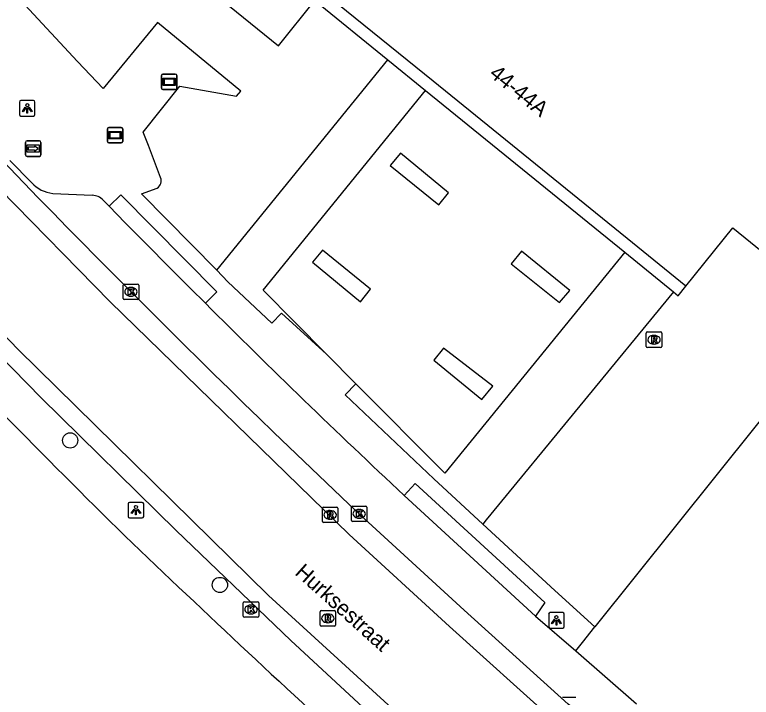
# Model space of a CAD drawing. Extents: x 157692 to 159670, y 381454 to 383289.
# Drawn here: x 157901.41 to 157948.81, y 382930.61 to 382974.54 of the extents above; entities that cross this region are included whole.
import ezdxf

# ---------------------------------------------------------------- set-up
doc = ezdxf.new("R2010")
doc.units = 0
for name, color, linetype in [('IMGEO_Boom', 7, 'Continuous'), ('IMGEO_Kolk', 7, 'Continuous'), ('IMGEO_Lichtpunt', 7, 'Continuous'), ('IMGEO_Openbare_ruimte_label', 7, 'Continuous'), ('IMGEO_Pand', 7, 'Continuous'), ('IMGEO_Pand_nummerreeks', 7, 'Continuous'), ('IMGEO_Parkeervlak_open', 7, 'Continuous'), ('IMGEO_Reclamebord', 7, 'Continuous'), ('IMGEO_Rijbaan_lokaal_gesloten', 7, 'Continuous'), ('IMGEO_Rijbaan_lokaal_open', 7, 'Continuous'), ('IMGEO_Rioolput', 7, 'Continuous'), ('IMGEO_Voetpad_open', 7, 'Continuous'), ('IMGEO_Wegwijzer', 7, 'Continuous')]:
    doc.layers.add(name, color=color, linetype=linetype)

msp = doc.modelspace()

# ---------------------------------------------------------------- linework, layer by layer
at = {"layer": 'IMGEO_Boom'}
for centre in [(157904.979, 382947.14), (157914.616, 382937.838)]:
    msp.add_circle(centre, 0.489, dxfattribs=at)
at = {"layer": 'IMGEO_Kolk'}
for p, q in [((157908.39, 382956.277), (157908.39, 382957.129)), ((157908.465, 382957.203), (157909.317, 382957.203)), ((157908.878, 382956.983), (157908.903, 382956.983)), ((157909.391, 382957.129), (157909.391, 382956.277)), ((157909.317, 382956.203), (157908.465, 382956.203)), ((157908.901, 382956.423), (157908.876, 382956.423)), ((157923.079, 382941.989), (157923.079, 382942.841)), ((157923.154, 382942.915), (157924.006, 382942.915)), ((157923.567, 382942.695), (157923.592, 382942.695)), ((157924.08, 382942.841), (157924.08, 382941.989)), ((157924.006, 382941.915), (157923.154, 382941.915)), ((157923.59, 382942.135), (157923.565, 382942.135)), ((157916.118, 382935.832), (157916.118, 382936.684)), ((157916.193, 382936.758), (157917.045, 382936.758)), ((157916.606, 382936.538), (157916.631, 382936.538)), ((157917.119, 382936.684), (157917.119, 382935.832)), ((157917.045, 382935.758), (157916.193, 382935.758)), ((157916.629, 382935.978), (157916.604, 382935.978)), ((157936.661, 382930.608), (157937.513, 382930.608))]:
    msp.add_line(p, q, dxfattribs=at)
for points in [[(157908.39, 382956.277), (157908.39, 382957.129)], [(157908.465, 382957.203), (157909.317, 382957.203)], [(157908.711, 382956.903), (157908.834, 382956.903), (157908.834, 382956.752), (157908.964, 382956.903), (157909.128, 382956.903), (157908.982, 382956.752), (157909.135, 382956.503), (157908.983, 382956.503), (157908.898, 382956.667), (157908.834, 382956.6), (157908.834, 382956.503), (157908.711, 382956.503), (157908.711, 382956.903)], [(157909.391, 382957.129), (157909.391, 382956.277)], [(157909.317, 382956.203), (157908.465, 382956.203)], [(157923.079, 382941.989), (157923.079, 382942.841)], [(157923.154, 382942.915), (157924.006, 382942.915)], [(157924.08, 382942.841), (157924.08, 382941.989)], [(157923.4, 382942.615), (157923.523, 382942.615), (157923.523, 382942.464), (157923.653, 382942.615), (157923.817, 382942.615), (157923.671, 382942.464), (157923.824, 382942.215), (157923.672, 382942.215), (157923.587, 382942.379), (157923.523, 382942.312), (157923.523, 382942.215), (157923.4, 382942.215), (157923.4, 382942.615)], [(157924.006, 382941.915), (157923.154, 382941.915)], [(157916.118, 382935.832), (157916.118, 382936.684)], [(157916.193, 382936.758), (157917.045, 382936.758)], [(157917.119, 382936.684), (157917.119, 382935.832)], [(157916.439, 382936.458), (157916.562, 382936.458), (157916.562, 382936.307), (157916.692, 382936.458), (157916.856, 382936.458), (157916.71, 382936.307), (157916.863, 382936.058), (157916.711, 382936.058), (157916.626, 382936.222), (157916.562, 382936.155), (157916.562, 382936.058), (157916.439, 382936.058), (157916.439, 382936.458)], [(157917.045, 382935.758), (157916.193, 382935.758)], [(157936.661, 382930.608), (157937.513, 382930.608)]]:
    msp.add_lwpolyline(points, dxfattribs=at)
for centre, start, end in [((157908.467, 382957.127), 91.552, 178.448), ((157908.467, 382957.127), 91.552, 178.448), ((157909.315, 382957.127), 1.552, 88.448), ((157909.315, 382957.127), 1.552, 88.448), ((157908.467, 382956.279), 181.552, 268.448), ((157908.467, 382956.279), 181.552, 268.448), ((157909.315, 382956.279), 271.552, 358.448), ((157909.315, 382956.279), 271.552, 358.448), ((157923.156, 382942.839), 91.552, 178.448), ((157923.156, 382942.839), 91.552, 178.448), ((157924.004, 382942.839), 1.552, 88.448), ((157924.004, 382942.839), 1.552, 88.448), ((157923.156, 382941.991), 181.552, 268.448), ((157923.156, 382941.991), 181.552, 268.448), ((157924.004, 382941.991), 271.552, 358.448), ((157924.004, 382941.991), 271.552, 358.448), ((157916.195, 382936.682), 91.552, 178.448), ((157916.195, 382936.682), 91.552, 178.448), ((157917.043, 382936.682), 1.552, 88.448), ((157917.043, 382936.682), 1.552, 88.448), ((157916.195, 382935.834), 181.552, 268.448), ((157916.195, 382935.834), 181.552, 268.448), ((157917.043, 382935.834), 271.552, 358.448), ((157917.043, 382935.834), 271.552, 358.448)]:
    msp.add_arc(centre, 0.0765, start, end, dxfattribs=at)
for centre, major_axis, ratio, start_param, end_param in [((157908.877, 382956.703), (-0.387, 0.002), 0.722429, 4.712389, 7.853982), ((157908.902, 382956.703), (-0.39, 0.002), 0.717154, 1.570796, 4.712389), ((157923.566, 382942.415), (-0.387, 0.002), 0.722429, 4.712389, 7.853982), ((157923.591, 382942.415), (-0.39, 0.002), 0.717154, 1.570796, 4.712389), ((157916.605, 382936.258), (-0.387, 0.002), 0.722429, 4.712389, 7.853982), ((157916.63, 382936.258), (-0.39, 0.002), 0.717154, 1.570796, 4.712389)]:
    msp.add_ellipse(centre, major_axis=major_axis, ratio=ratio, start_param=start_param, end_param=end_param, dxfattribs=at)
at = {"layer": 'IMGEO_Lichtpunt'}
for p, q in [((157901.721, 382968.92), (157901.721, 382968.113)), ((157901.721, 382968.92), (157901.721, 382968.113)), ((157902.623, 382969.015), (157901.815, 382969.015)), ((157902.623, 382969.015), (157901.815, 382969.015)), ((157902.717, 382968.113), (157902.717, 382968.92)), ((157902.717, 382968.113), (157902.717, 382968.92)), ((157901.815, 382968.019), (157902.623, 382968.019)), ((157901.815, 382968.019), (157902.623, 382968.019)), ((157908.715, 382943.06), (157908.715, 382942.253)), ((157908.715, 382943.06), (157908.715, 382942.253)), ((157909.617, 382943.155), (157908.809, 382943.155)), ((157909.617, 382943.155), (157908.809, 382943.155)), ((157909.711, 382942.253), (157909.711, 382943.06)), ((157909.711, 382942.253), (157909.711, 382943.06)), ((157908.809, 382942.159), (157909.617, 382942.159)), ((157908.809, 382942.159), (157909.617, 382942.159)), ((157936.676, 382936.06), (157935.868, 382936.06)), ((157936.676, 382936.06), (157935.868, 382936.06)), ((157935.774, 382935.965), (157935.774, 382935.158)), ((157935.774, 382935.965), (157935.774, 382935.158)), ((157936.77, 382935.158), (157936.77, 382935.965)), ((157936.77, 382935.158), (157936.77, 382935.965)), ((157935.868, 382935.064), (157936.676, 382935.064)), ((157935.868, 382935.064), (157936.676, 382935.064))]:
    msp.add_line(p, q, dxfattribs=at)
for points in [[(157902.095, 382968.584), (157902.134, 382968.556), (157901.946, 382968.294), (157901.908, 382968.321), (157902.095, 382968.584)], [(157902.197, 382968.536), (157902.244, 382968.536), (157902.244, 382968.214), (157902.197, 382968.214), (157902.197, 382968.536)], [(157902.307, 382968.556), (157902.345, 382968.583), (157902.532, 382968.321), (157902.493, 382968.293), (157902.307, 382968.556)], [(157909.089, 382942.724), (157909.128, 382942.696), (157908.94, 382942.434), (157908.902, 382942.461), (157909.089, 382942.724)], [(157909.301, 382942.696), (157909.339, 382942.723), (157909.526, 382942.461), (157909.487, 382942.433), (157909.301, 382942.696)], [(157909.191, 382942.676), (157909.238, 382942.676), (157909.238, 382942.354), (157909.191, 382942.354), (157909.191, 382942.676)], [(157936.148, 382935.629), (157936.187, 382935.601), (157935.999, 382935.339), (157935.961, 382935.366), (157936.148, 382935.629)], [(157936.25, 382935.581), (157936.297, 382935.581), (157936.297, 382935.259), (157936.25, 382935.259), (157936.25, 382935.581)], [(157936.36, 382935.601), (157936.398, 382935.628), (157936.585, 382935.366), (157936.546, 382935.338), (157936.36, 382935.601)]]:
    msp.add_lwpolyline(points, dxfattribs=at)
for centre in [(157902.22, 382968.718), (157909.214, 382942.858), (157936.273, 382935.763)]:
    msp.add_circle(centre, 0.0994, dxfattribs=at)
for centre, start, end in [((157901.815, 382968.92), 90, 180), ((157901.815, 382968.92), 90, 180), ((157902.623, 382968.92), 0, 90), ((157902.623, 382968.92), 0, 90), ((157901.815, 382968.113), 180, 270), ((157901.815, 382968.113), 180, 270), ((157902.623, 382968.113), 270, 0), ((157902.623, 382968.113), 270, 360), ((157908.809, 382943.06), 90, 180), ((157908.809, 382943.06), 90, 180), ((157909.617, 382943.06), 0, 90), ((157909.617, 382943.06), 0, 90), ((157908.809, 382942.253), 180, 270), ((157908.809, 382942.253), 180, 270), ((157909.617, 382942.253), 270, 0), ((157909.617, 382942.253), 270, 360), ((157935.868, 382935.965), 90, 180), ((157935.868, 382935.965), 90, 180), ((157936.676, 382935.965), 0, 90), ((157936.676, 382935.965), 0, 90), ((157935.868, 382935.158), 180, 270), ((157935.868, 382935.158), 180, 270), ((157936.676, 382935.158), 270, 0), ((157936.676, 382935.158), 270, 360)]:
    msp.add_arc(centre, 0.0946, start, end, dxfattribs=at)
at = {"layer": 'IMGEO_Pand'}
for points in [[(157944.604, 382957.079), (157941.167, 382959.865), (157928.338, 382970.263), (157921.096, 382976.133), (157924.661, 382980.529), (157909.579, 382992.763), (157909.075, 382992.142), (157904.647, 382995.734)], [(157944.604, 382957.079), (157947.635, 382960.816), (157951.722, 382957.5)]]:
    msp.add_lwpolyline(points, dxfattribs=at)
at = {"layer": 'IMGEO_Parkeervlak_open'}
for points in [[(157929.33, 382963.082), (157926.231, 382965.625), (157925.579, 382964.83), (157928.701, 382962.306), (157929.33, 382963.082)], [(157924.312, 382956.879), (157921.215, 382959.394), (157920.577, 382958.613), (157923.67, 382956.065), (157924.312, 382956.879)], [(157937.127, 382956.799), (157934.028, 382959.312), (157933.369, 382958.508), (157936.468, 382956.007), (157937.127, 382956.799)], [(157932.171, 382950.633), (157929.014, 382953.08), (157928.38, 382952.312), (157931.476, 382949.775), (157932.171, 382950.633)], [(157937.515, 382933.593), (157941.426, 382930.194)]]:
    msp.add_lwpolyline(points, dxfattribs=at)
at = {"layer": 'IMGEO_Reclamebord'}
for p, q in [((157910.955, 382970.723), (157911.745, 382970.723)), ((157911.745, 382970.723), (157910.955, 382970.723)), ((157910.855, 382969.823), (157910.855, 382970.623)), ((157910.855, 382970.623), (157910.855, 382969.823)), ((157911.845, 382970.623), (157911.845, 382969.823)), ((157911.845, 382969.823), (157911.845, 382970.623)), ((157911.745, 382969.723), (157910.955, 382969.723)), ((157910.955, 382969.723), (157911.745, 382969.723)), ((157907.373, 382966.386), (157907.373, 382967.186)), ((157907.373, 382967.186), (157907.373, 382966.386)), ((157907.473, 382967.286), (157908.263, 382967.286)), ((157908.263, 382967.286), (157907.473, 382967.286)), ((157908.363, 382967.186), (157908.363, 382966.386)), ((157908.363, 382966.386), (157908.363, 382967.186)), ((157908.263, 382966.286), (157907.473, 382966.286)), ((157907.473, 382966.286), (157908.263, 382966.286))]:
    msp.add_line(p, q, dxfattribs=at)
for points in [[(157910.956, 382970.455), (157911.744, 382970.455), (157911.744, 382969.991), (157910.956, 382969.991), (157910.956, 382970.455)], [(157911.021, 382970.39), (157911.021, 382970.056), (157911.679, 382970.056), (157911.679, 382970.39), (157911.021, 382970.39)], [(157907.474, 382967.018), (157908.262, 382967.018), (157908.262, 382966.554), (157907.474, 382966.554), (157907.474, 382967.018)], [(157907.539, 382966.953), (157907.539, 382966.619), (157908.197, 382966.619), (157908.197, 382966.953), (157907.539, 382966.953)]]:
    msp.add_lwpolyline(points, dxfattribs=at)
for centre, start, end in [((157910.955, 382970.623), 90, 180), ((157910.955, 382970.623), 90, 180), ((157911.745, 382970.623), 0, 90), ((157911.745, 382970.623), 360, 90), ((157910.955, 382969.823), 180, 270), ((157910.955, 382969.823), 180, 270), ((157911.745, 382969.823), 270, 0), ((157911.745, 382969.823), 270, 0), ((157907.473, 382967.186), 90, 180), ((157907.473, 382967.186), 90, 180), ((157908.263, 382967.186), 0, 90), ((157908.263, 382967.186), 360, 90), ((157907.473, 382966.386), 180, 270), ((157907.473, 382966.386), 180, 270), ((157908.263, 382966.386), 270, 0), ((157908.263, 382966.386), 270, 0)]:
    msp.add_arc(centre, 0.1, start, end, dxfattribs=at)
at = {"layer": 'IMGEO_Rijbaan_lokaal_gesloten'}
for points in [[(157947.967, 382910.552), (157946.644, 382911.702), (157931.39, 382924.697), (157917.745, 382937.164), (157901.645, 382952.982), (157887.528, 382967.671), (157876.832, 382979.322), (157871.708, 382985.081), (157860.333, 382998.307), (157856.331, 383002.954), (157848.451, 383012.068), (157848.333, 383012.223), (157843.229, 383018.142), (157838.644, 383023.478), (157833.658, 383029.315), (157818.224, 383047.235), (157807.775, 383059.411), (157802.275, 383065.844)], [(157850.521, 383024.905), (157853.541, 383017.962), (157856.251, 383014.213), (157856.467, 383013.904), (157862.032, 383006.673), (157867.395, 382999.837), (157867.54, 382999.666), (157867.971, 382999.126), (157869.317, 382997.443), (157870.868, 382995.617), (157882.451, 382982.543), (157892.691, 382971.484), (157900.441, 382963.318), (157907.565, 382956.05), (157922.939, 382941.093), (157929.386, 382935.17), (157936.105, 382929.105), (157938.637, 382926.944)], [(157880.505, 382973.291), (157884.414, 382969.188), (157893.988, 382959.187), (157903.105, 382949.871), (157911.795, 382941.344), (157919.191, 382934.261), (157926.716, 382927.298), (157940.793, 382914.946), (157946.658, 382909.821)], [(157939.553, 382928.003), (157937.039, 382930.159), (157930.329, 382936.205), (157923.89, 382942.12)]]:
    msp.add_lwpolyline(points, dxfattribs=at)
msp.add_arc((158379.787, 383426.039), 664.845, 223.019482, 226.707844, dxfattribs=at)
at = {"layer": 'IMGEO_Rijbaan_lokaal_open'}
for points in [[(157914.411, 382958.095), (157925.428, 382971.632)], [(157925.428, 382971.632), (157927.851, 382969.664)], [(157921.478, 382952.683), (157917.406, 382956.808), (157927.851, 382969.664)], [(157940.669, 382959.254), (157929.093, 382945.035), (157923.368, 382950.784)], [(157940.669, 382959.254), (157943.816, 382956.698)], [(157921.478, 382952.683), (157918.577, 382955.325), (157917.965, 382954.693), (157915.126, 382957.354), (157914.411, 382958.095)], [(157951.722, 382957.5), (157954.315, 382954.59), (157938.752, 382935.134)], [(157943.816, 382956.698), (157944.116, 382956.454), (157944.604, 382957.079)], [(157943.816, 382956.698), (157931.76, 382942.031), (157931.531, 382941.752)], [(157931.531, 382941.752), (157928.382, 382944.658), (157922.686, 382950.081), (157923.368, 382950.784)], [(157938.752, 382935.134), (157936.161, 382937.478), (157931.531, 382941.752)]]:
    msp.add_lwpolyline(points, dxfattribs=at)
at = {"layer": 'IMGEO_Rioolput'}
for p, q in [((157942.128, 382954.119), (157942.98, 382954.119)), ((157942.053, 382953.193), (157942.053, 382954.045)), ((157942.541, 382953.899), (157942.566, 382953.899)), ((157943.054, 382954.045), (157943.054, 382953.193)), ((157942.98, 382953.119), (157942.128, 382953.119)), ((157942.564, 382953.339), (157942.539, 382953.339)), ((157921.213, 382941.923), (157921.213, 382942.775)), ((157921.288, 382942.849), (157922.14, 382942.849)), ((157922.214, 382942.775), (157922.214, 382941.923)), ((157921.701, 382942.629), (157921.726, 382942.629)), ((157922.14, 382941.849), (157921.288, 382941.849)), ((157921.724, 382942.069), (157921.699, 382942.069)), ((157921.064, 382935.259), (157921.064, 382936.111)), ((157921.139, 382936.185), (157921.991, 382936.185)), ((157922.065, 382936.111), (157922.065, 382935.259)), ((157921.552, 382935.965), (157921.577, 382935.965)), ((157921.991, 382935.185), (157921.139, 382935.185)), ((157921.575, 382935.405), (157921.55, 382935.405))]:
    msp.add_line(p, q, dxfattribs=at)
for points in [[(157942.128, 382954.119), (157942.98, 382954.119)], [(157942.053, 382953.193), (157942.053, 382954.045)], [(157942.642, 382953.817), (157942.39, 382953.819), (157942.39, 382953.419)], [(157942.568, 382953.738), (157942.514, 382953.738), (157942.514, 382953.657)], [(157942.514, 382953.657), (157942.566, 382953.657)], [(157943.054, 382954.045), (157943.054, 382953.193)], [(157942.98, 382953.119), (157942.128, 382953.119)], [(157942.39, 382953.419), (157942.514, 382953.419), (157942.514, 382953.581), (157942.525, 382953.581)], [(157942.572, 382953.552), (157942.643, 382953.419), (157942.783, 382953.419), (157942.718, 382953.545)], [(157921.213, 382941.923), (157921.213, 382942.775)], [(157921.288, 382942.849), (157922.14, 382942.849)], [(157922.214, 382942.775), (157922.214, 382941.923)], [(157921.802, 382942.547), (157921.55, 382942.549), (157921.55, 382942.149)], [(157921.55, 382942.149), (157921.674, 382942.149), (157921.674, 382942.311), (157921.685, 382942.311)], [(157921.728, 382942.468), (157921.674, 382942.468), (157921.674, 382942.387)], [(157921.674, 382942.387), (157921.726, 382942.387)], [(157921.732, 382942.282), (157921.803, 382942.149), (157921.943, 382942.149), (157921.878, 382942.275)], [(157922.14, 382941.849), (157921.288, 382941.849)], [(157921.064, 382935.259), (157921.064, 382936.111)], [(157921.139, 382936.185), (157921.991, 382936.185)], [(157922.065, 382936.111), (157922.065, 382935.259)], [(157921.653, 382935.883), (157921.401, 382935.885), (157921.401, 382935.485)], [(157921.401, 382935.485), (157921.525, 382935.485), (157921.525, 382935.647), (157921.536, 382935.647)], [(157921.579, 382935.804), (157921.525, 382935.804), (157921.525, 382935.723)], [(157921.525, 382935.723), (157921.577, 382935.723)], [(157921.583, 382935.618), (157921.654, 382935.485), (157921.794, 382935.485), (157921.729, 382935.611)], [(157921.991, 382935.185), (157921.139, 382935.185)]]:
    msp.add_lwpolyline(points, dxfattribs=at)
for centre, radius, start, end in [((157942.13, 382954.043), 0.0765, 91.552, 178.448), ((157942.13, 382954.043), 0.0765, 91.552, 178.448), ((157942.978, 382954.043), 0.0765, 1.552, 88.448), ((157942.978, 382954.043), 0.0765, 1.552, 88.448), ((157942.55, 382953.846), 0.19, 274.7715, 282.9687), ((157942.574, 382953.642), 0.0964, 77.0061, 93.1865), ((157942.588, 382953.699), 0.0378, 276.6634, 79.6772), ((157942.641, 382953.707), 0.109, 350.3612, 89.416), ((157942.639, 382953.707), 0.112, 277.5842, 350.9817), ((157942.623, 382953.492), 0.108, 29.5134, 73.7905), ((157942.13, 382953.195), 0.0765, 181.552, 268.448), ((157942.13, 382953.195), 0.0765, 181.552, 268.448), ((157942.524, 382953.528), 0.0533, 26.0293, 88.6989), ((157942.978, 382953.195), 0.0765, 271.552, 358.448), ((157942.978, 382953.195), 0.0765, 271.552, 358.448), ((157921.29, 382942.773), 0.0765, 91.552, 178.448), ((157921.29, 382942.773), 0.0765, 91.552, 178.448), ((157922.138, 382942.773), 0.0765, 1.552, 88.448), ((157922.138, 382942.773), 0.0765, 1.552, 88.448), ((157921.684, 382942.258), 0.0533, 26.0293, 88.6989), ((157921.71, 382942.576), 0.19, 274.7715, 282.9687), ((157921.734, 382942.372), 0.0964, 77.0061, 93.1865), ((157921.748, 382942.429), 0.0378, 276.6634, 79.6772), ((157921.801, 382942.437), 0.109, 350.3612, 89.416), ((157921.799, 382942.437), 0.112, 277.5842, 350.9817), ((157921.783, 382942.222), 0.108, 29.5134, 73.7905), ((157921.29, 382941.925), 0.0765, 181.552, 268.448), ((157921.29, 382941.925), 0.0765, 181.552, 268.448), ((157922.138, 382941.925), 0.0765, 271.552, 358.448), ((157922.138, 382941.925), 0.0765, 271.552, 358.448), ((157921.141, 382936.109), 0.0765, 91.552, 178.448), ((157921.141, 382936.109), 0.0765, 91.552, 178.448), ((157921.989, 382936.109), 0.0765, 1.552, 88.448), ((157921.989, 382936.109), 0.0765, 1.552, 88.448), ((157921.535, 382935.594), 0.0533, 26.0293, 88.6989), ((157921.561, 382935.912), 0.19, 274.7715, 282.9687), ((157921.585, 382935.708), 0.0964, 77.0061, 93.1865), ((157921.599, 382935.765), 0.0378, 276.6634, 79.6772), ((157921.652, 382935.773), 0.109, 350.3612, 89.416), ((157921.65, 382935.773), 0.112, 277.5842, 350.9817), ((157921.634, 382935.558), 0.108, 29.5134, 73.7905), ((157921.141, 382935.261), 0.0765, 181.552, 268.448), ((157921.141, 382935.261), 0.0765, 181.552, 268.448), ((157921.989, 382935.261), 0.0765, 271.552, 358.448), ((157921.989, 382935.261), 0.0765, 271.552, 358.448)]:
    msp.add_arc(centre, radius, start, end, dxfattribs=at)
for centre, major_axis, ratio, start_param, end_param in [((157942.54, 382953.619), (-0.387, 0.002), 0.722429, 4.712389, 7.853982), ((157942.565, 382953.619), (-0.39, 0.002), 0.717154, 1.570796, 4.712389), ((157921.7, 382942.349), (-0.387, 0.002), 0.722429, 4.712389, 7.853982), ((157921.725, 382942.349), (-0.39, 0.002), 0.717154, 1.570796, 4.712389), ((157921.551, 382935.685), (-0.387, 0.002), 0.722429, 4.712389, 7.853982), ((157921.576, 382935.685), (-0.39, 0.002), 0.717154, 1.570796, 4.712389)]:
    msp.add_ellipse(centre, major_axis=major_axis, ratio=ratio, start_param=start_param, end_param=end_param, dxfattribs=at)
at = {"layer": 'IMGEO_Voetpad_open'}
for points in [[(157910.803, 382964.06), (157910.012, 382966.122), (157909.683, 382966.982), (157912.033, 382969.945), (157915.694, 382969.307), (157915.956, 382969.614), (157910.601, 382974.029), (157907.106, 382969.791), (157905.456, 382971.523), (157896.689, 382980.964), (157890.22, 382988.009), (157888.605, 382989.809), (157887.728, 382990.788), (157886.83, 382991.788), (157886.679, 382991.957), (157880.02, 383000), (157875.782, 383005.118), (157877.418, 383006.636)], [(157903.321, 382989.128), (157912.323, 382981.717), (157913.22, 382980.984), (157915.058, 382979.456), (157912.987, 382976.943), (157918.387, 382972.543), (157920.717, 382975.458), (157925.428, 382971.632)], [(157927.851, 382969.664), (157940.669, 382959.254)], [(157901.106, 382965.166), (157902.511, 382963.728)], [(157914.411, 382958.095), (157909.577, 382963.02), (157910.587, 382963.385)], [(157903.867, 382963.041), (157906.402, 382962.915)], [(157907.113, 382962.601), (157907.494, 382962.207)], [(157907.494, 382962.207), (157908.232, 382962.939), (157914.422, 382956.697), (157913.684, 382955.965)], [(157913.684, 382955.965), (157912.727, 382956.922), (157908.517, 382961.152), (157907.494, 382962.207)], [(157923.368, 382950.784), (157921.478, 382952.683)], [(157926.47, 382943.602), (157927.173, 382944.368), (157935.519, 382936.707), (157934.93, 382935.839)], [(157934.93, 382935.839), (157926.47, 382943.602)], [(157934.93, 382935.839), (157937.515, 382933.593)], [(157937.515, 382933.593), (157937.954, 382934.14), (157938.752, 382935.134)]]:
    msp.add_lwpolyline(points, dxfattribs=at)
for centre, radius, start, end in [((158701.069, 383738.472), 1124.351, 222.857272, 225.107447), ((157910.263, 382963.861), 0.576, 304.2857, 20.2249), ((157904.063, 382965.11), 2.078, 221.6746, 264.5885), ((157906.396, 382961.94), 0.975, 42.6756, 89.6689), ((158310.663, 383353.734), 561.972, 225.05691, 226.87031), ((158457.832, 383512.993), 793.053, 226.059637, 229.21244)]:
    msp.add_arc(centre, radius, start, end, dxfattribs=at)
at = {"layer": 'IMGEO_Wegwijzer'}
for p, q in [((157902.207, 382966.423), (157902.997, 382966.423)), ((157902.997, 382966.423), (157902.207, 382966.423)), ((157902.107, 382965.523), (157902.107, 382966.323)), ((157902.107, 382966.323), (157902.107, 382965.523)), ((157903.097, 382966.323), (157903.097, 382965.523)), ((157903.097, 382965.523), (157903.097, 382966.323)), ((157902.997, 382965.423), (157902.207, 382965.423)), ((157902.207, 382965.423), (157902.997, 382965.423))]:
    msp.add_line(p, q, dxfattribs=at)
for points in [[(157902.208, 382966.155), (157902.996, 382966.155), (157902.996, 382965.691), (157902.208, 382965.691), (157902.208, 382966.155)], [(157902.273, 382966.007), (157902.273, 382965.923), (157902.273, 382965.839), (157902.684, 382965.839), (157902.684, 382965.756), (157902.931, 382965.923), (157902.684, 382966.09), (157902.684, 382966.007), (157902.273, 382966.007)]]:
    msp.add_lwpolyline(points, dxfattribs=at)
for centre, start, end in [((157902.207, 382966.323), 90, 180), ((157902.207, 382966.323), 90, 180), ((157902.997, 382966.323), 0, 90), ((157902.997, 382966.323), 360, 90), ((157902.207, 382965.523), 180, 270), ((157902.207, 382965.523), 180, 270), ((157902.997, 382965.523), 270, 0), ((157902.997, 382965.523), 270, 0)]:
    msp.add_arc(centre, 0.1, start, end, dxfattribs=at)

# ---------------------------------------------------------------- texts
at = {"layer": 'IMGEO_Openbare_ruimte_label'}
msp.add_text('Hurksestraat', height=1, rotation=318.0809, dxfattribs=at).set_placement((157919.384, 382938.551))
at = {"layer": 'IMGEO_Pand_nummerreeks'}
msp.add_text('44-44A', height=1, rotation=320.9741, dxfattribs=at).set_placement((157931.89, 382970.628))

doc.saveas('drawing.dxf')
